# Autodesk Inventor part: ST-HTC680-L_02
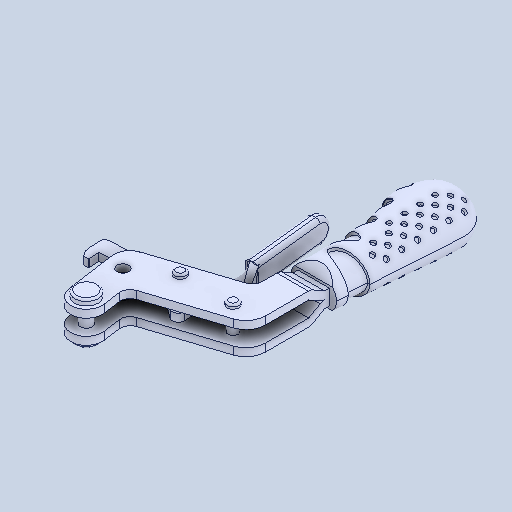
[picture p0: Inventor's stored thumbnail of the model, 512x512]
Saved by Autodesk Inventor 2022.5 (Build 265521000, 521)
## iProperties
Created: 2024-07
Part Number: ST-HTC680-L_02
Material: 一般
Document SubType Name: Modeling
Designer: ImaoCorp
Density: 1 g/cm^3
Appearance: 既定
Author: ImaoCorp
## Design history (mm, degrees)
feature "ST-HTC680-L_02"
node "ソリッド1"
